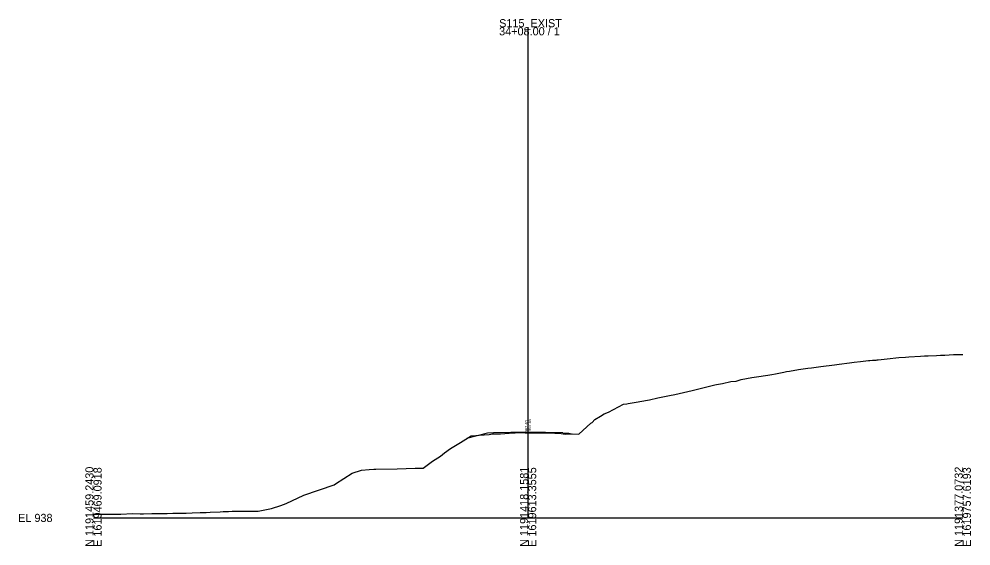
# Model space of a CAD drawing. Extents: x 1620351 to 1620680, y 1192592 to 1195749.
# Drawn here: x 1620351.1 to 1620679.6, y 1192591.8 to 1192773.7 of the extents above; entities that cross this region are included whole.
import ezdxf

# ---------------------------------------------------------------- set-up
doc = ezdxf.new("R2010")
doc.units = 0
for name, color, linetype in [('RD_GPK_XS_Cell', 7, 'Continuous'), ('RD_XS_EarthShd', 7, 'Continuous'), ('RD_XS_ExGround', 7, 'Continuous'), ('RD_XS_Pave', 7, 'Continuous'), ('RD_XS_TieSlope', 7, 'Continuous'), ('RD_XS_TX_Elev_EX', 7, 'Continuous'), ('RD_XS_TX_Elev_PR', 7, 'Continuous')]:
    doc.layers.add(name, color=color, linetype=linetype)

msp = doc.modelspace()

# ---------------------------------------------------------------- linework, layer by layer
at = {"layer": 'RD_GPK_XS_Cell'}
for p, q in [((1620526.76, 1192601.47), (1620526.76, 1192770.91)), ((1620376.76, 1192601.47), (1620526.76, 1192601.47)), ((1620526.76, 1192601.47), (1620676.76, 1192601.47))]:
    msp.add_line(p, q, dxfattribs=at)
at = {"layer": 'RD_XS_EarthShd'}
for p, q in [((1620514.76, 1192630.88), (1620512.76, 1192630.72)), ((1620538.76, 1192630.88), (1620540.76, 1192630.72))]:
    msp.add_line(p, q, dxfattribs=at)
at = {"layer": 'RD_XS_ExGround'}
msp.add_lwpolyline([(1620376.76, 1192602.73), (1620379.06, 1192602.75), (1620380.64, 1192602.71), (1620384.79, 1192602.76), (1620385.48, 1192602.74), (1620385.86, 1192602.73), (1620386.21, 1192602.76), (1620390.17, 1192602.93), (1620392.84, 1192602.89), (1620394.04, 1192602.87), (1620396.86, 1192602.96), (1620400.11, 1192602.99), (1620401.74, 1192603.04), (1620402.21, 1192603.04), (1620404.1, 1192603.07), (1620406.96, 1192603.1), (1620408.77, 1192603.15), (1620410.83, 1192603.23), (1620413.62, 1192603.31), (1620415.32, 1192603.32), (1620415.67, 1192603.34), (1620417.08, 1192603.43), (1620420.5, 1192603.59), (1620421.55, 1192603.66), (1620423.35, 1192603.68), (1620424.63, 1192603.74), (1620426.67, 1192603.82), (1620428.86, 1192603.74), (1620429.98, 1192603.76), (1620432.97, 1192603.81), (1620433.59, 1192603.81), (1620438.24, 1192604.73), (1620441.37, 1192605.76), (1620443.24, 1192606.41), (1620449.33, 1192609.32), (1620459.8, 1192612.92), (1620460.27, 1192613.22), (1620466.08, 1192616.92), (1620469.31, 1192617.98), (1620471.9, 1192618.22), (1620473.53, 1192618.26), (1620474.17, 1192618.29), (1620481.62, 1192618.42), (1620487.79, 1192618.61), (1620490.5, 1192618.69), (1620493.8, 1192621.01), (1620496.58, 1192622.84), (1620497.95, 1192623.97), (1620499.98, 1192625.45), (1620503.47, 1192627.56), (1620507.07, 1192629.84), (1620508.7, 1192629.94), (1620509.89, 1192630.04), (1620513.28, 1192630.32), (1620514.47, 1192630.47), (1620516.02, 1192630.5), (1620517.25, 1192630.55), (1620521.7, 1192630.79), (1620522.25, 1192630.82), (1620524.29, 1192630.91), (1620525.71, 1192630.87), (1620526.76, 1192630.87), (1620527.81, 1192630.86), (1620531.46, 1192630.87), (1620533.63, 1192630.84), (1620538.17, 1192630.56), (1620538.82, 1192630.53), (1620539.79, 1192630.42), (1620542.23, 1192630.47), (1620544.22, 1192630.41), (1620548.41, 1192634.23), (1620548.82, 1192634.47), (1620549.83, 1192635.44), (1620551.77, 1192636.57), (1620553, 1192637.37), (1620554.55, 1192638.03), (1620559.67, 1192640.73), (1620560.85, 1192640.87), (1620561.24, 1192640.92), (1620564.06, 1192641.48), (1620567.93, 1192642.18), (1620568.69, 1192642.24), (1620571.55, 1192642.94), (1620576.09, 1192643.82), (1620576.85, 1192643.95), (1620577.37, 1192644.09), (1620583.41, 1192645.52), (1620586.1, 1192646.18), (1620591.22, 1192647.39), (1620591.76, 1192647.53), (1620592.52, 1192647.67), (1620593.8, 1192647.9), (1620596.71, 1192648.58), (1620598.56, 1192648.72), (1620600.26, 1192649.24), (1620604.02, 1192649.92), (1620605.6, 1192650.21), (1620609.47, 1192650.76), (1620610.9, 1192650.97), (1620612.19, 1192651.19), (1620614.97, 1192651.78), (1620615.99, 1192651.98), (1620616.94, 1192652.13), (1620620.08, 1192652.68), (1620623.35, 1192653.13), (1620624.58, 1192653.31), (1620627.74, 1192653.74), (1620632.54, 1192654.35), (1620634.07, 1192654.59), (1620637.69, 1192655.07), (1620639.34, 1192655.26), (1620641.51, 1192655.53), (1620644.21, 1192655.81), (1620644.71, 1192655.85), (1620645.6, 1192655.9), (1620646.86, 1192655.97), (1620647.2, 1192656.01), (1620647.6, 1192656.04), (1620650.73, 1192656.38), (1620654.76, 1192656.88), (1620656.96, 1192656.98), (1620658.12, 1192657.05), (1620662.16, 1192657.31), (1620663.56, 1192657.4), (1620664.79, 1192657.42), (1620667.67, 1192657.55), (1620669.12, 1192657.62), (1620670.58, 1192657.71), (1620673.54, 1192657.85), (1620674.57, 1192657.89), (1620676.76, 1192657.95)], dxfattribs=at)
at = {"layer": 'RD_XS_Pave'}
for p, q in [((1620526.76, 1192631.12), (1620514.76, 1192630.88)), ((1620538.76, 1192630.88), (1620526.76, 1192631.12))]:
    msp.add_line(p, q, dxfattribs=at)
at = {"layer": 'RD_XS_TieSlope'}
for p, q in [((1620512.76, 1192630.72), (1620505.64, 1192628.94)), ((1620540.76, 1192630.72), (1620541.79, 1192630.46))]:
    msp.add_line(p, q, dxfattribs=at)

# ---------------------------------------------------------------- texts
at = {"layer": 'RD_GPK_XS_Cell'}
for s, p in [('S115_EXIST', (1620516.76, 1192770.91)), ('34+08.00 / 1', (1620516.76, 1192768.11)), ('EL 938', (1620350.76, 1192600.07))]:
    msp.add_text(s, height=2.8, dxfattribs=at).set_placement(p)
for s, p in [('N 1191459.2430', (1620376.76, 1192591.47)), ('E 1619469.0918', (1620379.56, 1192591.47)), ('N 1191418.1581', (1620526.76, 1192591.47)), ('E 1619613.3555', (1620529.56, 1192591.47)), ('N 1191377.0732', (1620676.76, 1192591.47)), ('E 1619757.6193', (1620679.56, 1192591.47))]:
    msp.add_text(s, height=2.8, rotation=90, dxfattribs=at).set_placement(p)
at = {"layer": 'RD_XS_TX_Elev_EX'}
msp.add_text('967.40', height=1, rotation=90, dxfattribs=at).set_placement((1620526.66, 1192630.97))
at = {"layer": 'RD_XS_TX_Elev_PR'}
msp.add_text(' 967.65', height=1, rotation=90, dxfattribs=at).set_placement((1620527.76, 1192631.12))

doc.saveas('drawing.dxf')
